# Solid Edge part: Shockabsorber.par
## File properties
Author: Türk
Template: Iso Part.par
Last saved by: Türk
Revision: 5
Application: Solid Edge
Accuracy: 0,990
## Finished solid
Body 1: sheet body, 1 face, 54 edges, 54 vertices.
  Faces by surface: plane 1
  Edges by curve: line 44, circle 10
Body 2: sheet body, 3 faces, 58 edges, 58 vertices.
  Faces by surface: plane 3
  Edges by curve: line 52, circle 6
Body 3: solid body, 54 faces, 118 edges, 64 vertices.
  Faces by surface: plane 26, cylinder 16, torus 10, cone 2
  Edges by curve: circle 46, line 40, intersection 28, ellipse 4
Bounding box of the edges (mm; curved faces can reach further): 110.000 x 222.500 x 110.000, from (-55, -87.5, -55) to (55, 135, 55).
Cylindrical faces by radius (mm): R10 x2, R20 x3, R22.5 x1, R25 x2, R28 x4, R30 x2, R51 x1, R55 x1
Conical faces (half-angle, radius in mm at the cone's reference point): 12.2648 deg R18.3163 x2
Toroidal faces (ring radius, tube radius in mm): R17.3807 r1.2 x2, R19.4889 r1.2 x2, R26.8 r1.2 x4, R30.5 r2.5 x1, R50 r5 x1
Planar faces by outward normal: +x 2, +y 9, +z 2, -x 2, -y 7, -z 2, oblique 2
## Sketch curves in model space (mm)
line (20, -75, 30) -> (20, -75, 19)
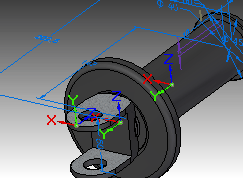
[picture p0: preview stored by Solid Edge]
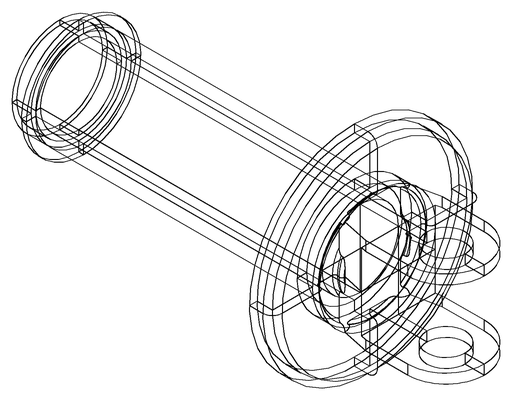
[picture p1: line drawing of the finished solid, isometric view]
